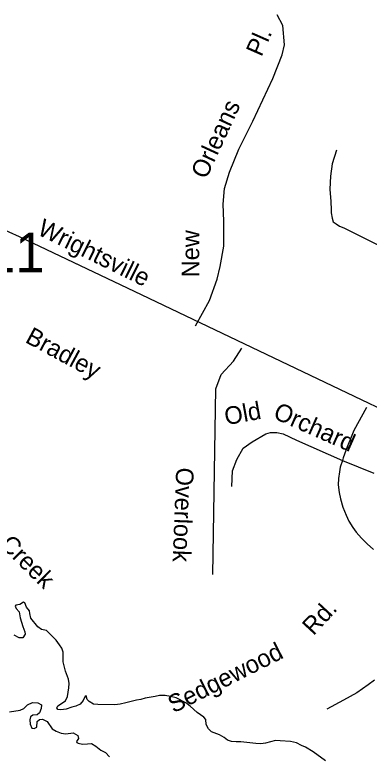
# Model space of a CAD drawing. Extents: x 1945482 to 2853149, y 66427 to 1015778.
# Drawn here: x 2350717 to 2352036, y 172048 to 174799 of the extents above; entities that cross this region are included whole.
import ezdxf

# ---------------------------------------------------------------- set-up
doc = ezdxf.new("R2010")
doc.units = 0
for name, color, linetype in [('Old_Level_10', 7, 'Continuous'), ('Old_Level_11', 7, 'Continuous'), ('Old_Level_21', 7, 'Continuous'), ('Old_Level_32', 7, 'Continuous'), ('Old_Level_35', 7, 'Continuous'), ('Old_Level_60', 7, 'Continuous'), ('Old_Level_8', 7, 'Continuous')]:
    doc.layers.add(name, color=color, linetype=linetype)

msp = doc.modelspace()

# ---------------------------------------------------------------- linework, layer by layer
at = {"layer": 'Old_Level_32'}
msp.add_lwpolyline([(2349442, 173589.6), (2349619.5, 173758.9), (2349812.9, 173941), (2349889.9, 174006.6), (2350020.9, 174083.7), (2350134.4, 174111.5), (2350247.7, 174128.1), (2350460.2, 174093.3), (2350539.2, 174060.6), (2350733.7, 173973.8), (2351161.4, 173771.4), (2352934.5, 172925.3)], dxfattribs=at)
at = {"layer": 'Old_Level_35'}
for points in [[(2351390, 173641.4), (2351441.4, 173735.7), (2351470.6, 173815.5), (2351481.2, 173863.3), (2351494.5, 173937.8), (2351494.5, 174030.9), (2351491.9, 174094.7), (2351497.2, 174153.2), (2351515.8, 174214.4), (2351550.3, 174299.5), (2351603.5, 174403.2), (2351677.9, 174562.8), (2351712.4, 174650.5), (2351720.4, 174687.8), (2351715.1, 174759.6), (2351693.8, 174799.5)], [(2351913.9, 174295.8), (2351897.9, 174245.3), (2351891.5, 174199.1), (2351889.4, 174151.1), (2351893.2, 174105), (2351894.5, 174074), (2351894.9, 174063), (2351897.7, 174043.1), (2351902.1, 174029.5), (2351912.6, 174021.7), (2351925.1, 174012.4), (2351941.1, 174007.1), (2352243.1, 173856.9)], [(2351454.2, 172717), (2351465.6, 173407.7), (2351484.7, 173461.2), (2351530.5, 173510.8), (2351562.5, 173558.9)], [(2352025.7, 173337.9), (2351979.2, 173252.1), (2351966.3, 173221.7), (2351953.4, 173191), (2351939.2, 173150.4), (2351936.2, 173140.8)], [(2351525.3, 173043.7), (2351527.2, 173102.3), (2351543.7, 173144.5), (2351567.5, 173186.7), (2351600.4, 173210.5), (2351651.7, 173239.8), (2351668.2, 173245.3), (2351692.1, 173245.3), (2351715.9, 173239.8), (2351765.3, 173216), (2351936.2, 173140.8)], [(2351936.2, 173140.8), (2351928.5, 173116.2), (2351925.2, 173098), (2351922.3, 173073.9), (2351920.9, 173049.9), (2351924.3, 173021.8), (2351929.2, 172998), (2351938.3, 172966.6), (2351949.7, 172936.8), (2351960.4, 172915.3), (2351975.4, 172891.9), (2351987.9, 172874.3), (2352006.9, 172851.1), (2352027.8, 172830), (2352052.5, 172809)], [(2351936.2, 173140.8), (2352052.9, 173093.7)], [(2352056, 172323), (2352032.4, 172306), (2351989.6, 172276.1), (2351940.8, 172248.2), (2351878.1, 172215.9)]]:
    msp.add_lwpolyline(points, dxfattribs=at)
at = {"layer": 'Old_Level_60'}
for points in [[(2350983.2, 172264.6), (2350978.7, 172263.4), (2350972, 172247.1), (2350960.7, 172234.2), (2350944.5, 172226.2), (2350928.7, 172222.7), (2350908.5, 172215.9), (2350888.2, 172212.7), (2350877.7, 172213.9), (2350873.2, 172220.4), (2350877, 172228.1), (2350905.7, 172246.3), (2350913, 172262.6), (2350918.2, 172294.1), (2350919.2, 172311.4), (2350916.7, 172326.7), (2350906, 172357.3), (2350896.7, 172391.2), (2350896.5, 172427.5), (2350892.5, 172441.8), (2350884, 172454.5), (2350871, 172471.7), (2350842.7, 172501), (2350834.5, 172508.1), (2350816.5, 172512.4), (2350803, 172522.3), (2350777.2, 172553.9), (2350773.5, 172571), (2350772.2, 172580.9), (2350760.5, 172594.7), (2350754.5, 172610.8), (2350749.5, 172613.8), (2350736, 172604.5), (2350721, 172602.5), (2350718.2, 172599.2), (2350722.2, 172590.4), (2350733, 172577.2), (2350736.5, 172555.8), (2350746.5, 172522.9), (2350754.7, 172503.4), (2350756, 172494.1), (2350746.7, 172481.3), (2350733.5, 172480.2), (2350714.2, 172490.8)], [(2351873, 172022.4), (2351828, 172056.5), (2351799.2, 172073.7), (2351783.5, 172080.4), (2351765.2, 172089.6), (2351743, 172094.7), (2351704.5, 172098), (2351686.7, 172098.7), (2351650, 172088.7), (2351632.5, 172086.7), (2351614.2, 172087.1), (2351558.2, 172093.7), (2351540.7, 172093.7), (2351523.5, 172095.5), (2351509.2, 172099.8), (2351496.5, 172109.4), (2351479, 172119.7), (2351449, 172131), (2351438.5, 172142.6), (2351428.7, 172158.2), (2351427.5, 172176.7), (2351421, 172185.2), (2351395.5, 172202.7), (2351369.7, 172226.6), (2351354, 172238.9), (2351317.2, 172257), (2351297, 172262.4), (2351276.5, 172265.7), (2351255, 172265.9), (2351239.5, 172262.5), (2351202.5, 172256.3), (2351185.7, 172250.9), (2351170, 172248.5), (2351130, 172238.4), (2351109, 172234.4), (2351089.5, 172231.6), (2351026.2, 172232.4), (2351009.5, 172234.2), (2350994.2, 172243.3), (2350986.5, 172251), (2350983.2, 172264.6)], [(2350697.2, 172205.9), (2350736.7, 172211.4), (2350750.2, 172218.3), (2350764.5, 172230.9), (2350783, 172240), (2350802.5, 172238.9), (2350816, 172232), (2350815, 172217.5), (2350809.5, 172201.6), (2350800.2, 172193.9), (2350784.2, 172192.5), (2350776, 172186.4), (2350772.5, 172175.4), (2350774.5, 172159.7), (2350780.2, 172145), (2350789.5, 172142.8), (2350798.7, 172148.9), (2350800.5, 172169.5), (2350808.7, 172177.4), (2350819.7, 172177.9), (2350838, 172169.5), (2350855.5, 172142.6), (2350871.5, 172133.6), (2350890, 172126), (2350907.5, 172123.3), (2350934.5, 172127.6), (2350951.5, 172117.6), (2350953.5, 172106.6), (2350947, 172094.8), (2350948, 172091.2), (2350952.7, 172088.5), (2350969, 172085.5), (2350988.2, 172086.9), (2351003, 172087), (2351018.7, 172077), (2351037.5, 172063.2), (2351054.7, 172053.7), (2351069.2, 172038.5)]]:
    msp.add_lwpolyline(points, dxfattribs=at)

# ---------------------------------------------------------------- texts
at = {"layer": 'Old_Level_10'}
for s, rotation, p in [('Pl.', 66.1902, (2351634.9, 174640.4)), ('Orleans', 65.1774, (2351429.2, 174184.7)), ('New', 90, (2351403.3, 173822.4)), ('Bradley', 331.7209, (2350752.1, 173582.3)), ('Old', 10.3461, (2351503.4, 173271.9)), ('Orchard', 336.1667, (2351674.6, 173299.6)), ('Overlook', 267.8519, (2351317.8, 173115.4)), ('Rd.', 47.2394, (2351828.6, 172486.5)), ('Sedgewood', 26.7563, (2351307.8, 172199.2))]:
    msp.add_text(s, height=65.62, rotation=rotation, dxfattribs=at).set_placement(p)
at = {"layer": 'Old_Level_11'}
msp.add_text('Wrightsville', height=65.617, rotation=333.8152, dxfattribs=at).set_placement((2350796.9, 173983.9))
at = {"layer": 'Old_Level_21'}
msp.add_text('East Prong Bradley Creek', height=65.617, rotation=315.1955, dxfattribs=at).set_placement((2350105.8, 173373.9))
at = {"layer": 'Old_Level_8'}
msp.add_text('1411', height=147.64, dxfattribs=at).set_placement((2350389.3, 173841.5))

doc.saveas('drawing.dxf')
